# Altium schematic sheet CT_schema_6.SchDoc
size 479 x 328 mm
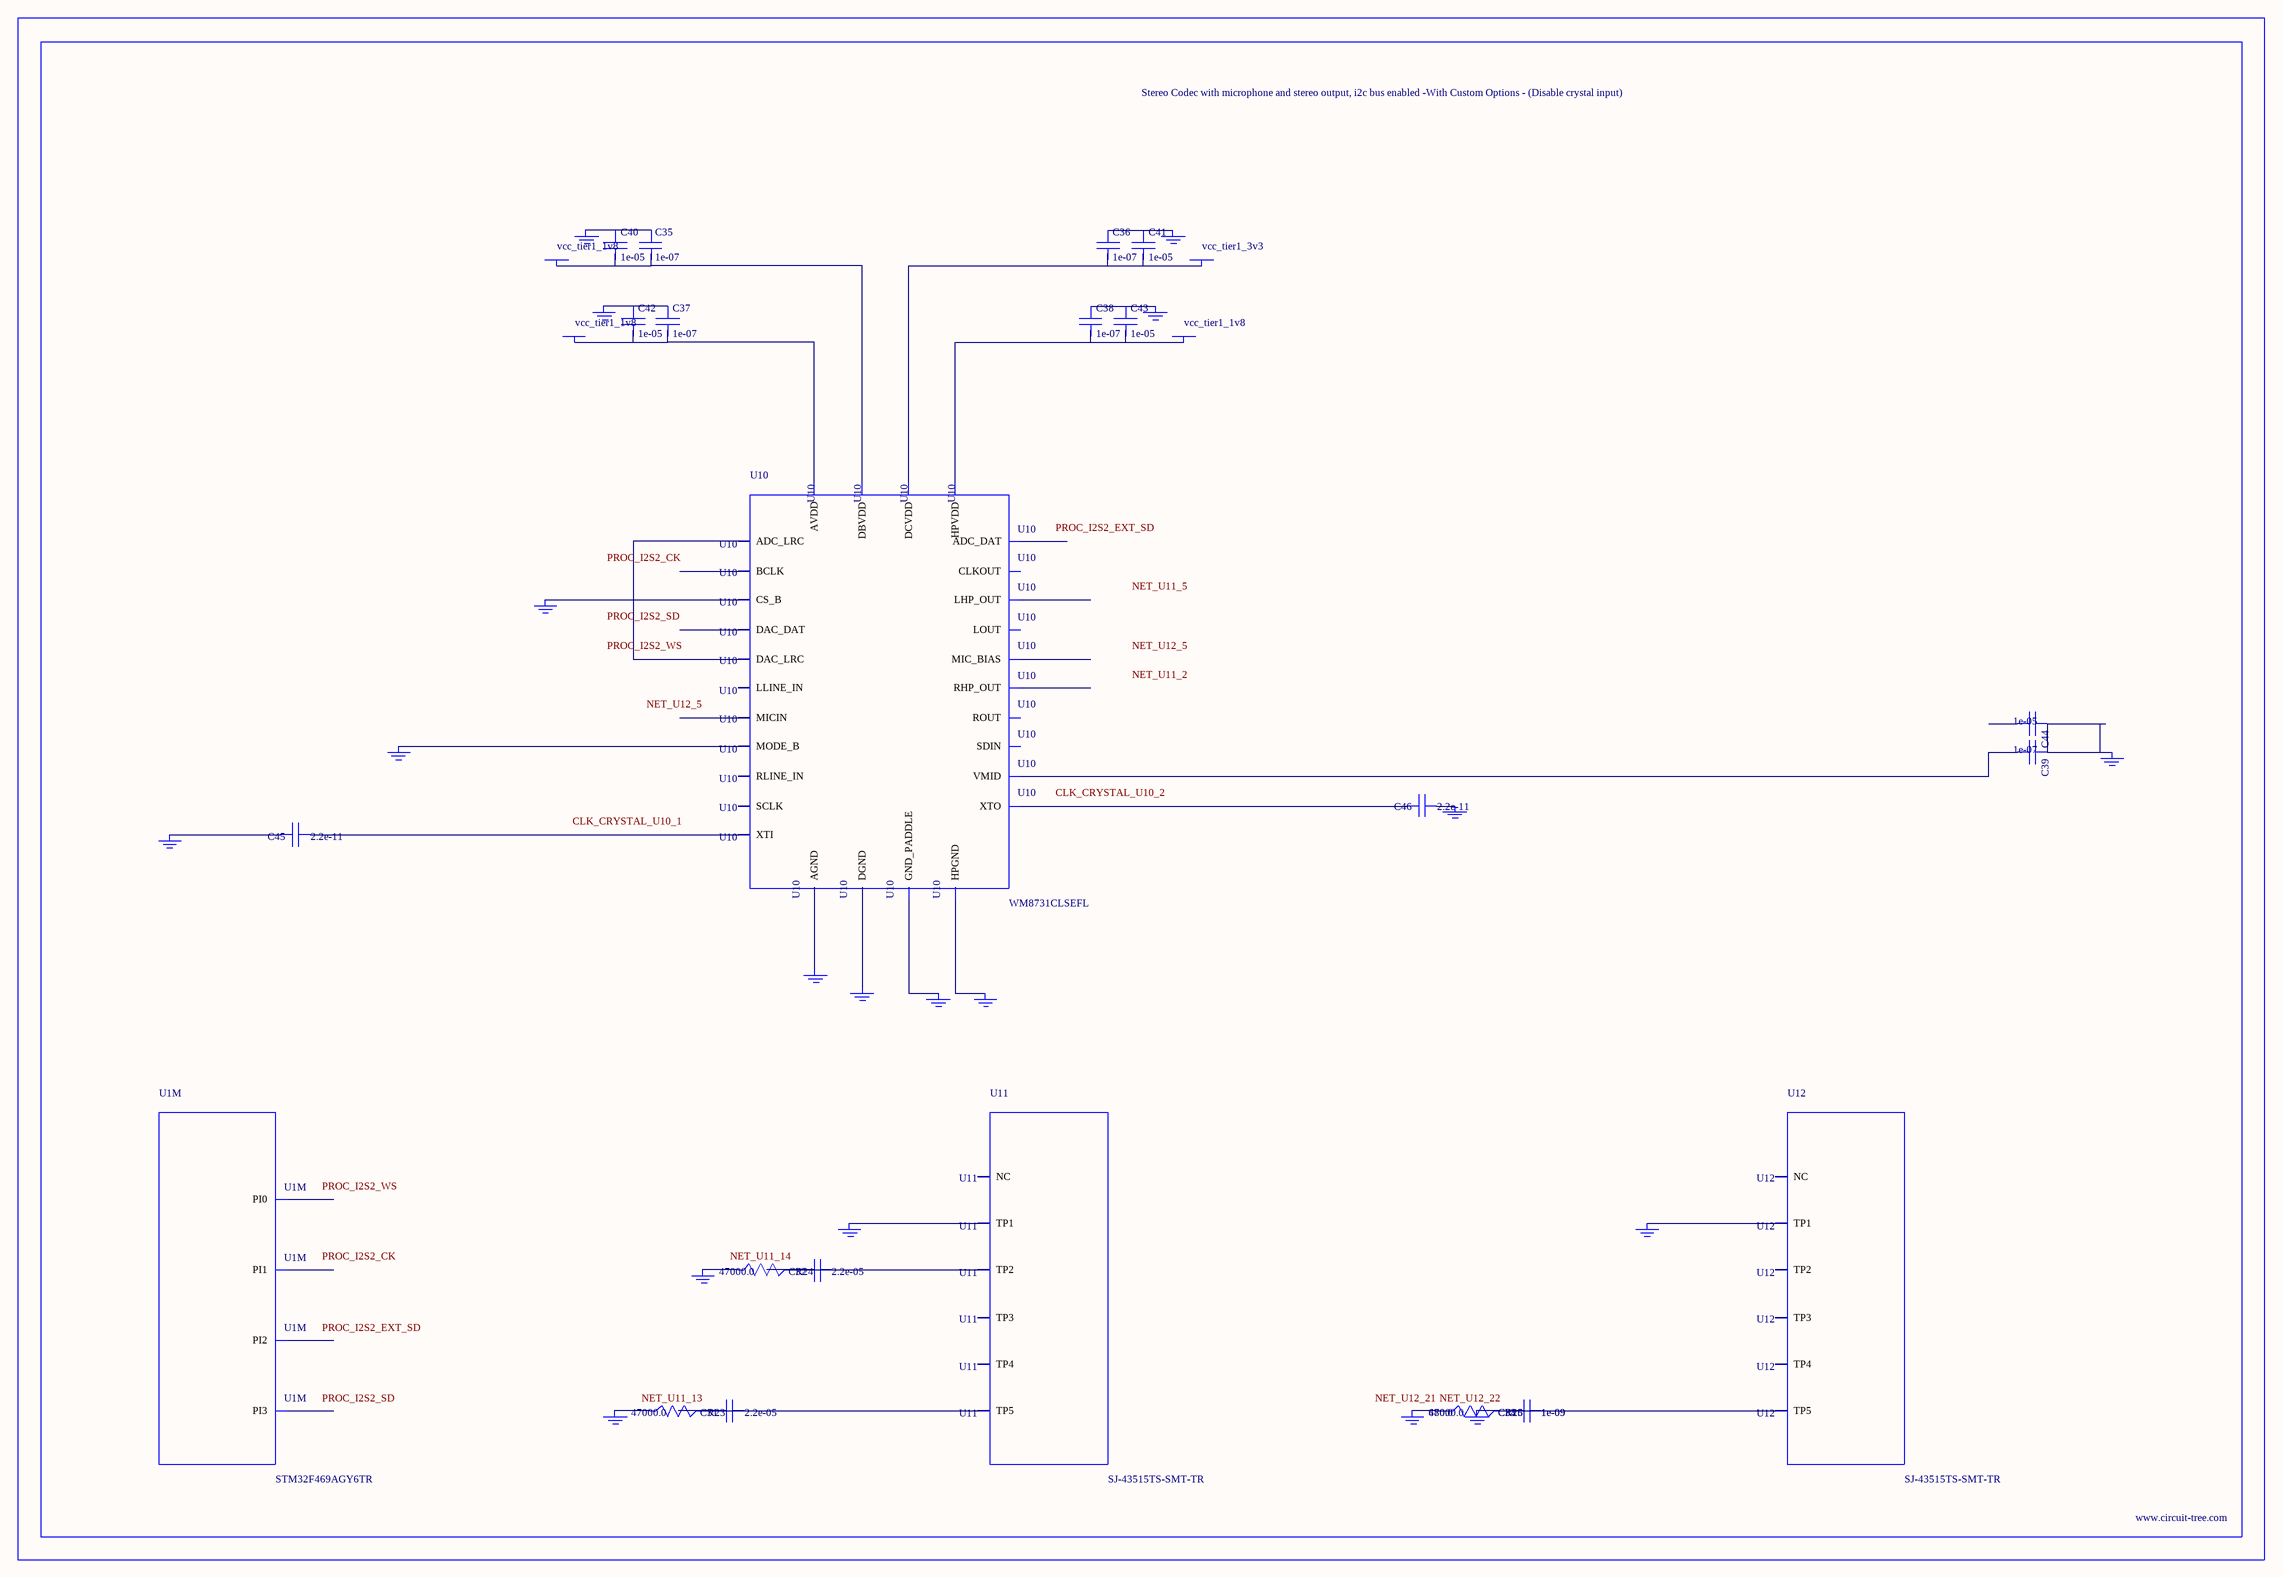
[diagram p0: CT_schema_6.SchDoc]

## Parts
BORDER5  (no value)
C31  2.2e-05  [C1210]
C32  2.2e-05  [C1210]
C33  1e-09  [C0402]
C34  1e-09  [C0402]
C35  1e-07  [C0402]
C36  1e-07  [C0402]
C37  1e-07  [C0402]
C38  1e-07  [C0402]
C39  1e-07  [C0402]
C40  1e-05  [C0805]
C41  1e-05  [C0805]
C42  1e-05  [C0805]
C43  1e-05  [C0805]
C44  1e-05  [C0805]
C45  2.2e-11  [C0402]
C46  2.2e-11  [C0402]
GND_INSTANCE_5_0  (no value)
GND_INSTANCE_5_1  (no value)
GND_INSTANCE_5_2  (no value)
GND_INSTANCE_5_3  (no value)
GND_INSTANCE_5_4  (no value)
GND_INSTANCE_5_5  (no value)
GND_INSTANCE_5_6  (no value)
GND_INSTANCE_5_7  (no value)
GND_INSTANCE_5_8  (no value)
GND_INSTANCE_5_9  (no value)
GND_INSTANCE_5_10  (no value)
GND_INSTANCE_5_11  (no value)
GND_INSTANCE_5_12  (no value)
GND_INSTANCE_5_13  (no value)
GND_INSTANCE_5_14  (no value)
GND_INSTANCE_5_15  (no value)
GND_INSTANCE_5_16  (no value)
GND_INSTANCE_5_17  (no value)
GND_INSTANCE_5_18  (no value)
POWER_INSTANCE_5_0  vcc_tier1_3v3
POWER_INSTANCE_5_1  vcc_tier1_1v8
POWER_INSTANCE_5_2  vcc_tier1_1v8
POWER_INSTANCE_5_3  vcc_tier1_1v8
R23  47000.0  [R0603]
R24  47000.0  [R0603]
R25  47000.0  [R0603]
R26  680.0  [R0603]
U1  STM32F469AGY6TR  [WLCSP168]  (part M of 13)
U10  WM8731CLSEFL  [QFN-28]
U11  SJ-43515TS-SMT-TR  [SJ-43515TS-SMT-TR]
U12  SJ-43515TS-SMT-TR  [SJ-43515TS-SMT-TR]

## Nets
NetC31_1: C31.1 C31.2 R23.2 U11.5(TP5)
NetC32_1: C32.1 C32.2 R24.2 U11.2(TP2)
NetC33_1: C33.1 C33.2 C34.1 C34.2 GND_INSTANCE_5_18.0(GND) R25.2 R26.2 U12.5(TP5)
NetC35_1: C35.1 C40.1 GND_INSTANCE_5_3.0(GND)
NetC35_2: C35.2 C40.2 POWER_INSTANCE_5_1.0(PWR) U10.5(DBVDD)
NetC36_1: C36.1 C41.1 GND_INSTANCE_5_2.0(GND)
NetC36_2: C36.2 C41.2 POWER_INSTANCE_5_0.0(PWR) U10.3(DCVDD)
NetC37_1: C37.1 C42.1 GND_INSTANCE_5_6.0(GND)
NetC37_2: C37.2 C42.2 POWER_INSTANCE_5_3.0(PWR) U10.18(AVDD)
NetC38_1: C38.1 C43.1 GND_INSTANCE_5_4.0(GND)
NetC38_2: C38.2 C43.2 POWER_INSTANCE_5_2.0(PWR) U10.12(HPVDD)
NetC39_1: C39.1 C44.1 GND_INSTANCE_5_7.0(GND)
NetC39_2: C39.2 U10.20(VMID)
NetC45_1: C45.1 U10.1(XTI)
NetC45_2: C45.2 GND_INSTANCE_5_0.0(GND)
NetC46_1: C46.1 GND_INSTANCE_5_1.0(GND)
NetC46_2: C46.2 U10.2(XTO)
NetGND_INSTANCE_5_5_0: GND_INSTANCE_5_5.0(GND) U10.15(HPGND)
NetGND_INSTANCE_5_8_0: GND_INSTANCE_5_8.0(GND) U10.25(MODE_B)
NetGND_INSTANCE_5_9_0: GND_INSTANCE_5_9.0(GND) U10.26(CS_B)
NetGND_INSTANCE_5_10_0: GND_INSTANCE_5_10.0(GND) U10.29(GND_PADDLE)
NetGND_INSTANCE_5_11_0: GND_INSTANCE_5_11.0(GND) U10.4(DGND)
NetGND_INSTANCE_5_12_0: GND_INSTANCE_5_12.0(GND) U10.19(AGND)
NetGND_INSTANCE_5_13_0: GND_INSTANCE_5_13.0(GND) U11.1(TP1)
NetGND_INSTANCE_5_14_0: GND_INSTANCE_5_14.0(GND) R24.1
NetGND_INSTANCE_5_15_0: GND_INSTANCE_5_15.0(GND) R23.1
NetGND_INSTANCE_5_16_0: GND_INSTANCE_5_16.0(GND) U12.1(TP1)
NetGND_INSTANCE_5_17_0: GND_INSTANCE_5_17.0(GND) R25.1 R26.1
NetU10_9: U10.9(DAC_LRC) U10.11(ADC_LRC)

Not connected (* = marked no-connect by the designer): C44 2; U1 A1(PI2) B2(PI3) C3(PI1) E5(PI0); U10 6(CLKOUT) 7(BCLK) 8(DAC_DAT) 10(ADC_DAT) 13(LHP_OUT) 14(RHP_OUT) 16(LOUT) 17(ROUT) 21(MIC_BIAS) 22(MICIN) 23(RLINE_IN) 24(LLINE_IN) 27(SDIN) 28(SCLK); U11 3(TP3) 4(TP4) 6(NC); U12 2(TP2) 3(TP3) 4(TP4) 6(NC)

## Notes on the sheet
- Labels drawn without touching a wire or pin: CLK_CRYSTAL_U10_1, CLK_CRYSTAL_U10_2, NET_U11_2, NET_U11_5, NET_U11_13, NET_U11_14, NET_U12_5, NET_U12_21, NET_U12_22, PROC_I2S2_CK, PROC_I2S2_EXT_SD, PROC_I2S2_SD, PROC_I2S2_WS

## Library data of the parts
BORDER5 = BORDER_PAGE5
C31 C32 = C1210C224K5RACTU
C33 C34 = C0402C102K3RAC
C35-C39 = C0402C104K3RACTU
C40-C44 = C0805C106K8RACTU
C45 C46 = C0402C220K3RAC
GND_INSTANCE_5_0-GND_INSTANCE_5_18 = GND
POWER_INSTANCE_5_0-POWER_INSTANCE_5_3 = PWR
R23-R25 = RC0603JR-0747KL
R26 = RC0603JR-07680RL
